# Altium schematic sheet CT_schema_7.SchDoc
size 251 x 159 mm
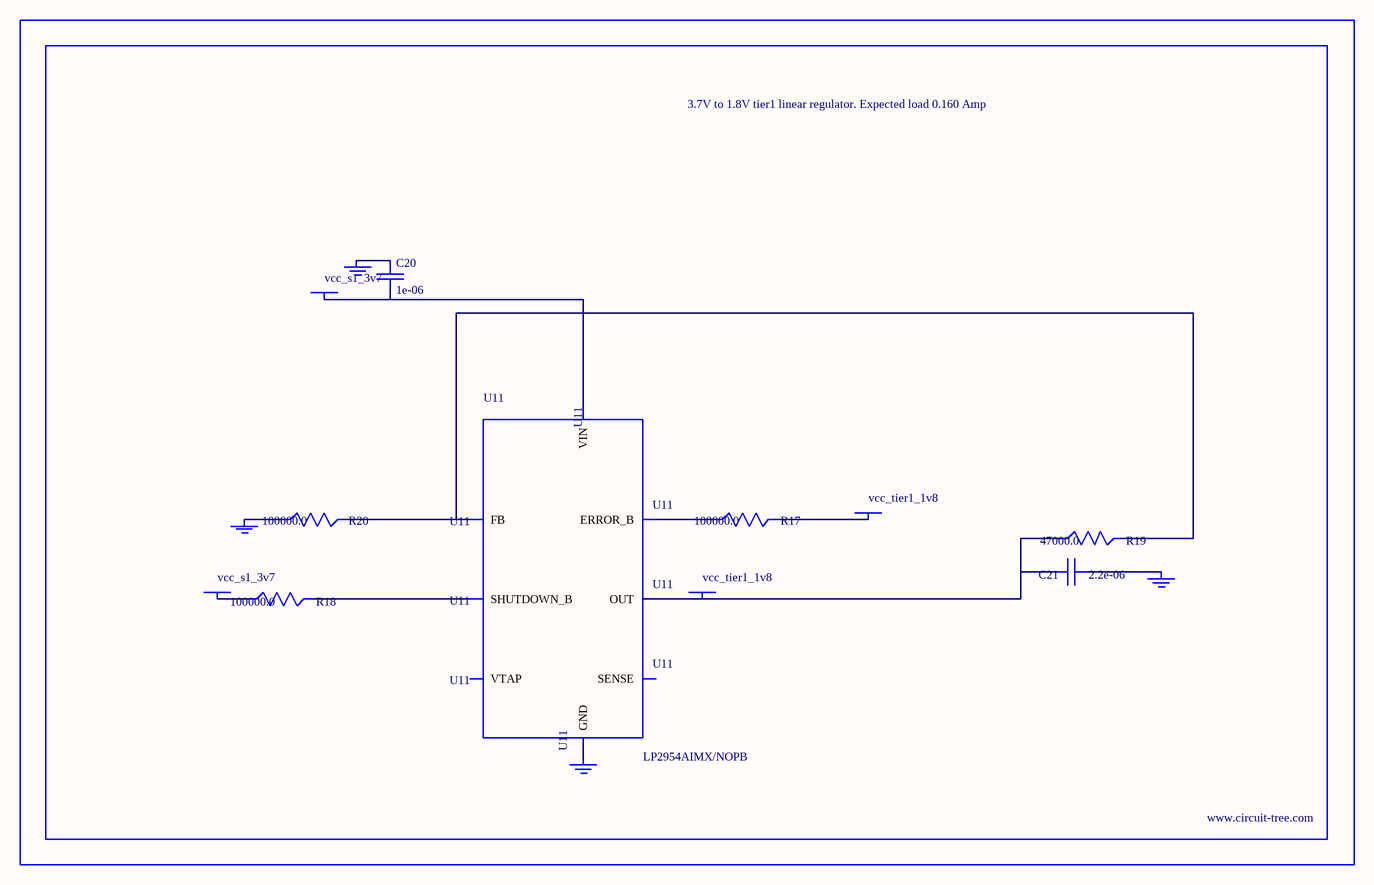
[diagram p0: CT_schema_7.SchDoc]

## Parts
BORDER6  (no value)
C20  1e-06  [EXV-9B]
C21  2.2e-06  [EXV-9B]
GND_INSTANCE_6_0  (no value)
GND_INSTANCE_6_1  (no value)
GND_INSTANCE_6_2  (no value)
GND_INSTANCE_6_3  (no value)
POWER_INSTANCE_6_0  vcc_s1_3v7
POWER_INSTANCE_6_1  vcc_tier1_1v8
POWER_INSTANCE_6_2  vcc_s1_3v7
POWER_INSTANCE_6_3  vcc_tier1_1v8
R17  100000.0  [R0603]
R18  100000.0  [R0603]
R19  47000.0  [R0603]
R20  100000.0  [R0603]
U11  LP2954AIMX/NOPB  [LP2954]

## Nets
NetC20_1: C20.1 GND_INSTANCE_6_2.0(GND)
NetC20_2: C20.2 POWER_INSTANCE_6_2.0(PWR) U11.8(VIN)
NetC21_1: C21.1 GND_INSTANCE_6_0.0(GND)
NetC21_2: C21.2 POWER_INSTANCE_6_3.0(PWR) R19.1 U11.1(OUT)
NetGND_INSTANCE_6_1_0: GND_INSTANCE_6_1.0(GND) R20.1
NetGND_INSTANCE_6_3_0: GND_INSTANCE_6_3.0(GND) U11.4(GND)
NetPOWER_INSTANCE_6_0_0: POWER_INSTANCE_6_0.0(PWR) R18.1
NetPOWER_INSTANCE_6_1_0: POWER_INSTANCE_6_1.0(PWR) R17.2
NetR17_1: R17.1 U11.5(ERROR_B)
NetR18_2: R18.2 U11.3(SHUTDOWN_B)
NetR19_2: R19.2 R20.2 U11.7(FB)

Not connected (* = marked no-connect by the designer): U11 2(SENSE) 6(VTAP)

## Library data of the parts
BORDER6 = BORDER_PAGE6
C20 = EDK105M050A9BAA
C21 = EDK225M050A9BAA
GND_INSTANCE_6_0-GND_INSTANCE_6_3 = GND
POWER_INSTANCE_6_0-POWER_INSTANCE_6_3 = PWR
R17 R18 R20 = RC0603JR-07100KL
R19 = RC0603JR-0747KL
